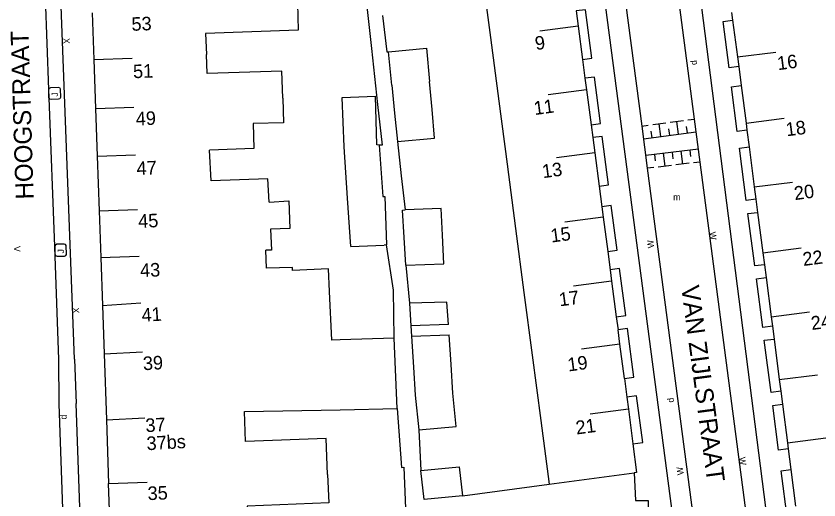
# Model space of a CAD drawing. Extents: x 134999 to 136502, y 457398 to 459002.
# Drawn here: x 135974.8 to 136037.3, y 457543.2 to 457580.9 of the extents above; entities that cross this region are included whole.
import ezdxf

# ---------------------------------------------------------------- set-up
doc = ezdxf.new("R2010")
doc.units = 0
for name, color, linetype in [('RI_DGTB_15', 7, 'Continuous'), ('RI_DGTB_29', 7, 'Continuous'), ('RI_DGTB_30', 7, 'Continuous'), ('RI_DGTB_31', 7, 'Continuous'), ('RI_DGTB_35', 7, 'Continuous'), ('RI_DGTB_36', 7, 'Continuous'), ('RI_DGTB_37', 7, 'Continuous'), ('RI_DGTB_4', 7, 'Continuous'), ('RI_DGTB_43', 7, 'Continuous'), ('RI_DGTB_5', 7, 'Continuous'), ('RI_DGTB_53', 7, 'Continuous'), ('RI_DGTB_54', 7, 'Continuous'), ('RI_DGTB_6', 7, 'Continuous')]:
    doc.layers.add(name, color=color, linetype=linetype)

msp = doc.modelspace()

# ---------------------------------------------------------------- linework, layer by layer
at = {"layer": 'RI_DGTB_15'}
for p, q in [((136018.517, 457580.097), (136015.542, 457579.71)), ((136030.916, 457577.693), (136033.892, 457578.071)), ((135980.824, 457577.485), (135983.822, 457577.602)), ((136019.168, 457575.144), (136016.193, 457574.758)), ((135980.957, 457573.677), (135983.955, 457573.793)), ((136031.585, 457572.551), (136034.561, 457572.929)), ((135981.086, 457569.97), (135984.084, 457570.086)), ((136019.813, 457570.236), (136016.838, 457569.85)), ((136032.23, 457567.59), (136035.206, 457567.968)), ((135981.234, 457565.721), (135984.232, 457565.837)), ((136020.472, 457565.23), (136017.497, 457564.843)), ((136032.897, 457562.466), (136035.873, 457562.844)), ((135981.36, 457562.093), (135984.358, 457562.209)), ((136021.124, 457560.267), (136018.149, 457559.88)), ((135981.49, 457558.371), (135984.483, 457558.574)), ((136033.544, 457557.488), (136036.52, 457557.866)), ((136021.769, 457555.356), (136018.794, 457554.969)), ((135981.629, 457554.594), (135984.618, 457554.773)), ((136034.174, 457552.606), (136037.15, 457552.984)), ((136022.43, 457550.304), (136019.454, 457549.917)), ((135981.808, 457549.466), (135984.804, 457549.64)), ((136034.809, 457547.697), (136037.785, 457548.075)), ((135981.965, 457544.516), (135984.978, 457544.633))]:
    msp.add_line(p, q, dxfattribs=at)
at = {"layer": 'RI_DGTB_31'}
for p, q in [((136024.321, 457572.429), (136025.349, 457572.567)), ((136024.968, 457571.507), (136024.835, 457572.498)), ((136025.691, 457572.613), (136026.719, 457572.751)), ((136026.338, 457571.691), (136026.205, 457572.682)), ((136027.062, 457572.797), (136027.576, 457572.866)), ((136023.464, 457572.314), (136023.978, 457572.383)), ((136023.597, 457571.323), (136027.709, 457571.875)), ((136024.282, 457571.415), (136024.216, 457571.911)), ((136025.653, 457571.599), (136025.586, 457572.095)), ((136027.024, 457571.783), (136026.957, 457572.279)), ((136027.895, 457570.531), (136023.776, 457570.039)), ((136024.462, 457570.121), (136024.522, 457569.618)), ((136025.149, 457570.203), (136025.269, 457569.197)), ((136025.835, 457570.285), (136025.895, 457569.782)), ((136026.522, 457570.367), (136026.642, 457569.361)), ((136027.208, 457570.449), (136027.268, 457569.946)), ((136027.157, 457569.422), (136026.127, 457569.3)), ((136028.015, 457569.525), (136027.5, 457569.464)), ((136024.411, 457569.094), (136023.896, 457569.033)), ((136025.784, 457569.258), (136024.754, 457569.136)), ((135977.788, 457562.934), (135977.787, 457562.956))]:
    msp.add_line(p, q, dxfattribs=at)
for points in [[(135977.354, 457574.505), (135977.343, 457574.522), (135977.321, 457575.149), (135977.329, 457575.164)], [(135977.329, 457575.164), (135977.378, 457575.259), (135977.487, 457575.317), (135978.054, 457575.337), (135978.158, 457575.306), (135978.225, 457575.222), (135978.249, 457574.531), (135978.196, 457574.437), (135978.094, 457574.403), (135978.086, 457574.404), (135977.519, 457574.384), (135977.407, 457574.422), (135977.354, 457574.505)], [(135977.788, 457562.934), (135977.809, 457562.328), (135977.873, 457562.228), (135977.985, 457562.19), (135978.552, 457562.21), (135978.56, 457562.209), (135978.662, 457562.243), (135978.715, 457562.337), (135978.691, 457563.029), (135978.623, 457563.113), (135978.52, 457563.144), (135977.953, 457563.124), (135977.844, 457563.066), (135977.787, 457562.956)]]:
    msp.add_lwpolyline(points, dxfattribs=at)
at = {"layer": 'RI_DGTB_4'}
for p, q in [((136018.362, 457581.278), (136018.517, 457580.097)), ((135980.698, 457581.119), (135980.824, 457577.485)), ((136030.467, 457581.151), (136030.545, 457580.551)), ((136018.517, 457580.097), (136018.858, 457577.501)), ((136030.545, 457580.551), (136030.917, 457577.693)), ((135980.824, 457577.485), (135980.959, 457573.677)), ((136018.858, 457577.501), (136019.051, 457576.034)), ((136030.917, 457577.693), (136031.015, 457576.942)), ((136031.015, 457576.942), (136031.205, 457575.475)), ((136019.051, 457576.034), (136019.168, 457575.144)), ((136019.168, 457575.144), (136019.526, 457572.423)), ((136031.205, 457575.475), (136031.585, 457572.551)), ((135980.959, 457573.677), (135981.086, 457569.97)), ((136031.585, 457572.551), (136031.657, 457571.995)), ((136019.526, 457572.423), (136019.657, 457571.421)), ((136031.657, 457571.995), (136031.826, 457570.696)), ((136019.657, 457571.421), (136019.813, 457570.236)), ((136031.826, 457570.696), (136032.231, 457567.59)), ((135981.086, 457569.97), (135981.238, 457565.721)), ((136019.813, 457570.236), (136020.153, 457567.652)), ((136020.153, 457567.652), (136020.364, 457566.045)), ((136032.231, 457567.59), (136032.356, 457566.628)), ((136032.356, 457566.628), (136032.488, 457565.608)), ((135981.238, 457565.721), (135981.365, 457562.093)), ((136020.364, 457566.045), (136020.471, 457565.23)), ((136032.488, 457565.608), (136032.897, 457562.466)), ((136020.471, 457565.23), (136020.822, 457562.563)), ((136020.822, 457562.563), (136021.009, 457561.144)), ((136032.897, 457562.466), (136033.017, 457561.541)), ((135981.365, 457562.093), (135981.496, 457558.371)), ((136033.017, 457561.541), (136033.147, 457560.539)), ((136021.009, 457561.144), (136021.124, 457560.267)), ((136021.124, 457560.267), (136021.49, 457557.484)), ((136033.147, 457560.539), (136033.543, 457557.488)), ((135981.496, 457558.371), (135981.629, 457554.594)), ((136021.49, 457557.484), (136021.623, 457556.473)), ((136033.543, 457557.488), (136033.637, 457556.76)), ((136021.769, 457555.356), (136021.623, 457556.473)), ((136033.637, 457556.76), (136033.766, 457555.759)), ((136004.193, 457555.835), (136000, 457555.702)), ((136004.444, 457550.344), (136004.193, 457555.835)), ((136033.766, 457555.759), (136034.174, 457552.606)), ((136022.118, 457552.693), (136021.769, 457555.356)), ((135981.629, 457554.594), (135981.808, 457549.466)), ((136022.118, 457552.693), (136022.307, 457551.244)), ((136034.174, 457552.606), (136034.292, 457551.692)), ((136022.307, 457551.244), (136022.43, 457550.304)), ((136034.292, 457551.692), (136034.424, 457550.681)), ((136034.424, 457550.681), (136034.809, 457547.697)), ((136000, 457550.257), (136004.444, 457550.344)), ((136022.43, 457550.304), (136022.781, 457547.614)), ((135981.808, 457549.466), (135981.965, 457544.516)), ((136034.809, 457547.697), (136034.872, 457547.208)), ((136034.872, 457547.208), (136035.079, 457545.602)), ((136035.079, 457545.602), (136035.447, 457542.765)), ((135982.15, 457539.686), (135981.965, 457544.516))]:
    msp.add_line(p, q, dxfattribs=at)
msp.add_lwpolyline([(136022.781, 457547.614), (136023.073, 457545.379), (136022.875, 457545.353)], dxfattribs=at)
at = {"layer": 'RI_DGTB_5'}
for p, q in [((136011.034, 457584.177), (136011.688, 457579.209)), ((136011.688, 457579.209), (136012.34, 457574.258)), ((136012.34, 457574.258), (136012.987, 457569.35)), ((136012.987, 457569.35), (136013.646, 457564.342)), ((136013.646, 457564.342), (136014.3, 457559.379)), ((136014.3, 457559.379), (136014.941, 457554.512)), ((136000, 457555.702), (135999.366, 457555.678)), ((136014.941, 457554.512), (136015.612, 457549.417)), ((135992.553, 457550.128), (136000, 457550.257)), ((136015.612, 457549.417), (136016.263, 457544.472)), ((136016.263, 457544.472), (136022.875, 457545.353))]:
    msp.add_line(p, q, dxfattribs=at)
for points in [[(135996.689, 457581.861), (135996.727, 457579.784), (135989.531, 457579.517), (135989.592, 457577.896)], [(135995.529, 457574.494), (135995.474, 457576.601), (135989.648, 457576.415), (135989.592, 457577.896)], [(135995.529, 457574.494), (135995.58, 457572.578), (135993.236, 457572.523), (135993.292, 457570.584), (135989.831, 457570.448)], [(135994.464, 457566.413), (135994.378, 457568.227), (135989.957, 457568.072), (135989.831, 457570.448)], [(135994.464, 457566.413), (135996.002, 457566.499), (135996.079, 457564.361), (135994.585, 457564.304), (135994.646, 457562.677), (135994.225, 457562.658)], [(135996.294, 457561.097), (135996.287, 457561.333), (135994.282, 457561.259), (135994.225, 457562.658)], [(135999.159, 457559.462), (135999.087, 457561.212), (135996.294, 457561.097)], [(135999.366, 457555.678), (135999.159, 457559.462)], [(135999.022, 457545.216), (135998.913, 457548.016), (135992.63, 457547.78), (135992.553, 457550.128)], [(135999.022, 457545.216), (135999.107, 457543.031), (135992.753, 457542.755), (135992.84, 457540.48), (135994.677, 457540.524), (135994.702, 457540.326)]]:
    msp.add_lwpolyline(points, dxfattribs=at)
at = {"layer": 'RI_DGTB_53'}
for p, q in [((135977.329, 457575.164), (135976.524, 457596.625)), ((135977.354, 457574.505), (135977.329, 457575.164)), ((135977.787, 457562.956), (135977.354, 457574.505)), ((135977.788, 457562.934), (135977.787, 457562.956)), ((135979.327, 457554.201), (135979.45, 457550.753))]:
    msp.add_line(p, q, dxfattribs=at)
for points in [[(136020.053, 457598.22), (136023.464, 457572.314)], [(136023.464, 457572.314), (136023.896, 457569.033)], [(136023.896, 457569.033), (136032.394, 457504.482)], [(135978.448, 457541.827), (135978.135, 457550.707), (135978.117, 457554.156), (135977.788, 457562.934)]]:
    msp.add_lwpolyline(points, dxfattribs=at)
at = {"layer": 'RI_DGTB_54'}
for p, q in [((135979.327, 457554.201), (135977.747, 457596.327)), ((136000.811, 457593.027), (136002.436, 457578.352)), ((136002.436, 457578.352), (136002.918, 457574)), ((136005.121, 457561.507), (136005.391, 457558.537)), ((136006.118, 457548.708), (136006.276, 457545.524)), ((136009.509, 457543.561), (136016.263, 457544.472))]:
    msp.add_line(p, q, dxfattribs=at)
for points in [[(136022.871, 457608.685), (136022.976, 457608.493), (136023.126, 457608.334), (136024.765, 457607.7), (136034.926, 457528.466), (136033.865, 457527.72), (136033.699, 457527.563), (136033.596, 457527.358), (136033.571, 457527.233)], [(136027.576, 457572.866), (136022.871, 457608.685)], [(136020.053, 457598.22), (136018.629, 457596.95), (136030.3, 457508.3)], [(136018.858, 457577.501), (136019.597, 457577.594), (136019.102, 457581.368), (136018.362, 457581.278)], [(136003.295, 457580.91), (136003.638, 457578.086), (136003.774, 457578.099)], [(136031.015, 457576.942), (136030.272, 457576.848), (136029.803, 457580.454), (136030.545, 457580.551)], [(136019.526, 457572.423), (136020.264, 457572.519), (136019.79, 457576.129), (136019.051, 457576.034)], [(136031.657, 457571.995), (136030.905, 457571.898), (136030.453, 457575.378), (136031.205, 457575.475)], [(136002.918, 457574), (136003.268, 457570.842), (136003.045, 457570.832)], [(136028.015, 457569.525), (136027.576, 457572.866)], [(136020.153, 457567.652), (136020.891, 457567.747), (136020.397, 457571.508), (136019.657, 457571.421)], [(136004.468, 457571.122), (136004.743, 457568.456), (136005.052, 457565.793)], [(136032.356, 457566.628), (136031.602, 457566.534), (136031.072, 457570.599), (136031.826, 457570.696)], [(136033.571, 457527.233), (136028.015, 457569.525)], [(136020.822, 457562.563), (136021.555, 457562.657), (136021.101, 457566.14), (136020.364, 457566.045)], [(136033.017, 457561.541), (136032.262, 457561.445), (136031.734, 457565.511), (136032.488, 457565.608)], [(136004.193, 457555.835), (136004.144, 457559.568), (136003.609, 457563.078)], [(136021.49, 457557.484), (136022.227, 457557.58), (136021.746, 457561.24), (136021.009, 457561.144)], [(136033.637, 457556.76), (136032.884, 457556.662), (136032.392, 457560.442), (136033.147, 457560.539)], [(136005.498, 457556.797), (136005.548, 457555.983)], [(136022.118, 457552.693), (136022.86, 457552.787), (136022.366, 457556.569), (136021.623, 457556.473)], [(136034.292, 457551.692), (136033.532, 457551.593), (136033.006, 457555.661), (136033.766, 457555.759)], [(136022.781, 457547.614), (136023.544, 457547.711), (136023.071, 457551.343), (136022.307, 457551.244)], [(135975.2, 457470.43), (135978.741, 457475.827), (135979.402, 457477.074), (135979.991, 457478.357), (135980.248, 457478.984), (135980.638, 457480.438), (135980.951, 457481.91), (135981.184, 457483.397), (135981.339, 457484.894), (135981.413, 457486.397), (135981.408, 457487.902), (135981.389, 457488.395), (135981.218, 457495.745), (135980.358, 457525.044), (135979.45, 457550.753)], [(136034.872, 457547.208), (136034.111, 457547.117), (136033.662, 457550.584), (136034.424, 457550.681)], [(136004.444, 457550.344), (136004.764, 457545.778), (136004.957, 457545.788), (136005.176, 457540.655)], [(136035.568, 457541.833), (136034.807, 457541.735), (136034.32, 457545.505), (136035.079, 457545.602)], [(136022.875, 457545.353), (136022.994, 457543.201), (136023.96, 457543.211), (136023.935, 457539.898), (136023.183, 457539.828)]]:
    msp.add_lwpolyline(points, dxfattribs=at)
at = {"layer": 'RI_DGTB_6'}
for p, q in [((136000.153, 457574.53), (136002.75, 457574.651)), ((136000.575, 457566.716), (136000.325, 457570.701)), ((136000.828, 457562.957), (136003.431, 457563.063)), ((136008.422, 457556.888), (136005.498, 457556.797)), ((136005.548, 457555.983), (136008.476, 457556.075))]:
    msp.add_line(p, q, dxfattribs=at)
for points in [[(136003.774, 457578.099), (136006.716, 457578.371), (136006.956, 457575.78)], [(136004.014, 457575.508), (136003.774, 457578.099)], [(136007.15, 457573.616), (136006.956, 457575.78)], [(136004.014, 457575.508), (136004.241, 457573.315)], [(136000.325, 457570.701), (136000.153, 457574.53)], [(136002.867, 457570.852), (136002.75, 457574.651)], [(136004.241, 457573.315), (136004.468, 457571.122)], [(136004.468, 457571.122), (136007.349, 457571.388), (136007.15, 457573.616)], [(136003.045, 457570.832), (136002.867, 457570.852)], [(136003.045, 457570.832), (136003.309, 457566.852), (136003.482, 457566.845), (136003.609, 457563.078), (136003.431, 457563.063)], [(136000.828, 457562.957), (136000.575, 457566.716)], [(136004.986, 457563.646), (136004.852, 457565.784), (136005.052, 457565.793)], [(136007.959, 457563.832), (136007.85, 457565.919), (136005.052, 457565.793)], [(136005.121, 457561.507), (136008.075, 457561.613), (136007.959, 457563.832)], [(136005.121, 457561.507), (136004.986, 457563.646)], [(136008.422, 457556.888), (136008.306, 457558.628), (136005.391, 457558.537)], [(136005.391, 457558.537), (136005.498, 457556.797)], [(136005.548, 457555.983), (136005.696, 457553.563)], [(136008.629, 457553.773), (136008.476, 457556.075)], [(136006.118, 457548.708), (136009.016, 457548.945), (136008.777, 457551.556), (136008.629, 457553.773)], [(136005.696, 457553.563), (136005.828, 457551.4), (136006.118, 457548.708)], [(136006.276, 457545.524), (136009.255, 457545.817), (136009.509, 457543.561)], [(136009.509, 457543.561), (136006.541, 457543.269), (136006.276, 457545.524)]]:
    msp.add_lwpolyline(points, dxfattribs=at)

# ---------------------------------------------------------------- texts
at = {"layer": 'RI_DGTB_29'}
for height, rotation, p in [(0.5, 97.47758, (136027.78, 457577.096)), (0.5, 97.47758, (136025.989, 457550.846)), (0.499, 92.01159, (135978.718, 457549.512))]:
    msp.add_text('d', height=height, rotation=rotation, dxfattribs=at).set_placement(p)
at = {"layer": 'RI_DGTB_30'}
for s, height, rotation, p in [('X', 0.5, 271.66989, (135978.446, 457579.157)), ('W', 0.499, 277.47626, (136028.729, 457564.063)), ('W', 0.5, 97.41219, (136024.445, 457562.862)), ('V', 0.499, 271.98141, (135974.604, 457562.979)), ('X', 0.5, 271.66989, (135979.184, 457558.198)), ('W', 0.499, 277.47626, (136031.03, 457546.546)), ('W', 0.5, 97.41219, (136026.745, 457545.211))]:
    msp.add_text(s, height=height, rotation=rotation, dxfattribs=at).set_placement(p)
at = {"layer": 'RI_DGTB_31'}
for p in [(135978.046, 457574.61), (135978.512, 457562.417)]:
    msp.add_text('J', height=0.5, rotation=90, dxfattribs=at).set_placement(p)
at = {"layer": 'RI_DGTB_35'}
msp.add_text('21', height=1.054, rotation=7.4988, dxfattribs=at).set_placement((136018.402, 457548.332))
at = {"layer": 'RI_DGTB_36'}
for s, rotation, p in [('53', 1.9845, (135983.779, 457579.723)), ('9', 7.4988, (136015.23, 457578.223)), ('16', 7.4061, (136034.077, 457576.663)), ('51', 1.9827, (135983.902, 457576.039)), ('11', 7.4988, (136015.14, 457573.175)), ('49', 1.9809, (135984.114, 457572.369)), ('18', 7.4061, (136034.746, 457571.52)), ('47', 1.9791, (135984.174, 457568.514)), ('13', 7.4988, (136015.785, 457568.266)), ('20', 7.4061, (136035.39, 457566.559)), ('45', 1.9771, (135984.301, 457564.404)), ('15', 7.4988, (136016.444, 457563.259)), ('22', 7.4061, (136036.058, 457561.435)), ('43', 1.9757, (135984.449, 457560.576)), ('17', 7.4988, (136017.096, 457558.297)), ('41', 3.6362, (135984.58, 457557.089)), ('24', 7.4061, (136036.705, 457556.457)), ('39', 3.1881, (135984.68, 457553.329)), ('19', 7.4988, (136017.762, 457553.231)), ('37', 3.3064, (135984.878, 457548.512)), ('37bs', 3.2428, (135984.962, 457547.107)), ('35', 1.962, (135985.033, 457543.228))]:
    msp.add_text(s, height=1.054, rotation=rotation, dxfattribs=at).set_placement(p)
at = {"layer": 'RI_DGTB_37'}
for s, rotation, p in [('HOOGSTRAAT', 91.75621, (135976.151, 457566.634)), ('VAN ZIJLSTRAAT', 277.57917, (136026.534, 457559.835))]:
    msp.add_text(s, height=1.4, rotation=rotation, dxfattribs=at).set_placement(p)
at = {"layer": 'RI_DGTB_43'}
msp.add_text('m', height=0.5, dxfattribs=at).set_placement((136025.92, 457566.548))

doc.saveas('drawing.dxf')
